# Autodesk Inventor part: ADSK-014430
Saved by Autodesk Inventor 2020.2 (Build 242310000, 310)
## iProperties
Part Number: ADSK-014430
Material: Allgemein
Description: Framegenerator-Skeleton-Referenz
Document SubType Name: Modellieren
Designer: lutzd
Density: 1 g/cm^3
Appearance: Vorgabe
_SkeletonDoc: Frame Skeleton File
_Version: 15.0.0
Title: Gestellrahmenbauteil(e)
Author: lutzd
Revision Number: -
DocNumber: ADSK-014430
Folder: .
Mass: 0 lb
VLT_Material: Generisch
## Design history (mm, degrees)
node "Referenzrahmen"
node "Volumenkörper"
node "Flächenkörper"
